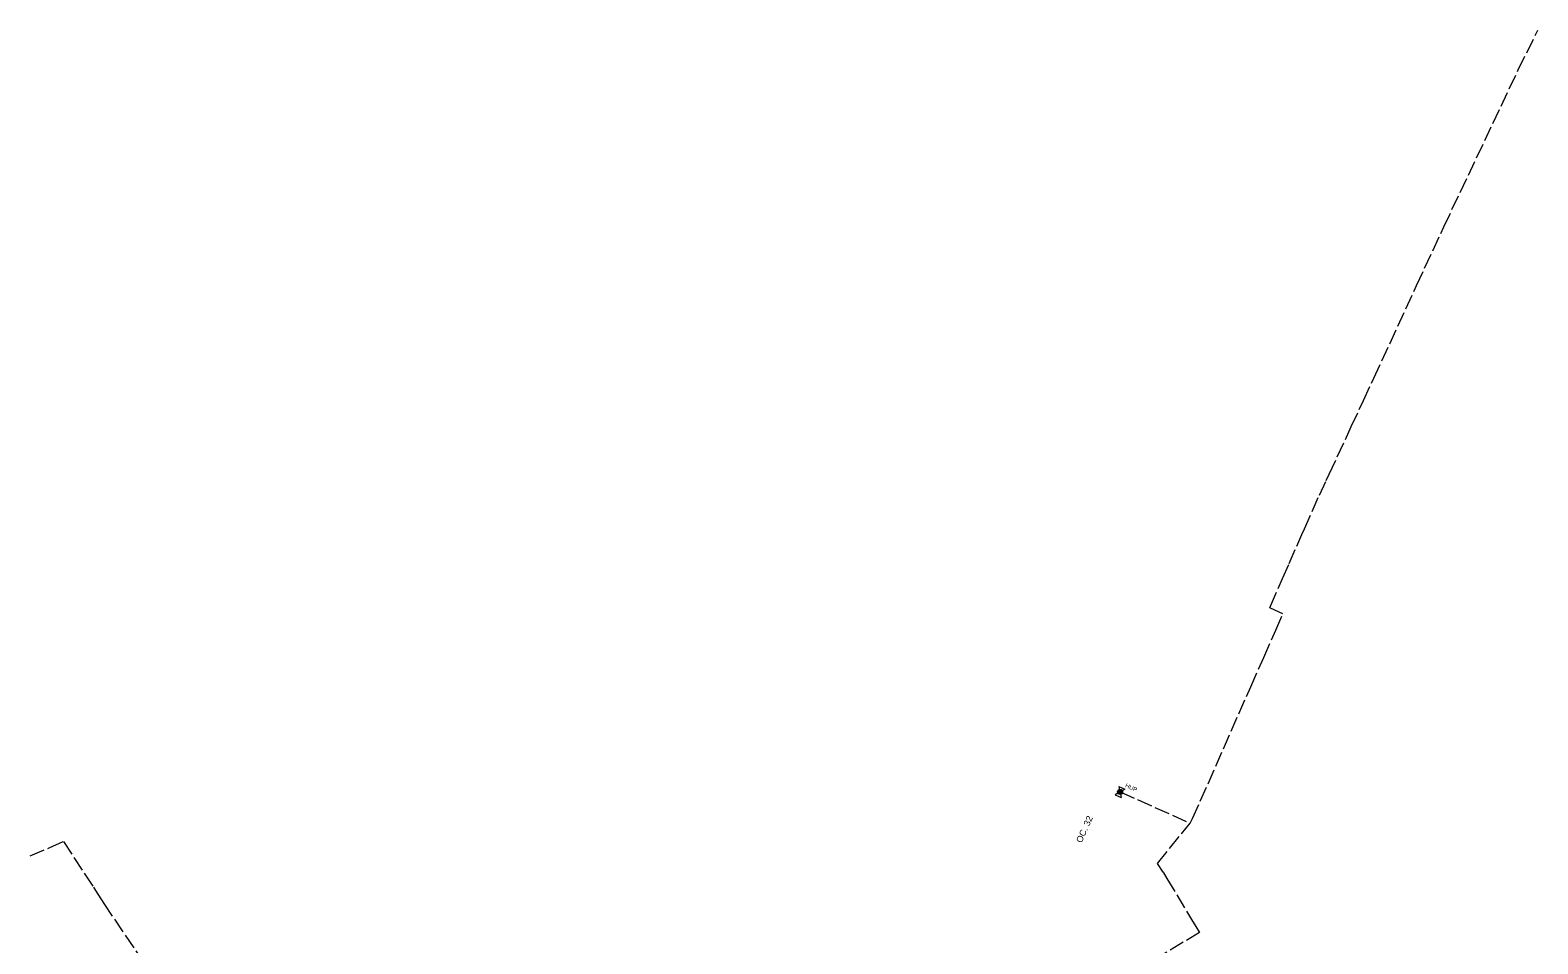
# Model space of a CAD drawing. Extents: x -688140 to -687678, y -1056859 to -1056384.
# Drawn here: x -688068.5 to -687890.7, y -1056491.8 to -1056384.1 of the extents above; entities that cross this region are included whole.
import ezdxf
from ezdxf.enums import TextEntityAlignment as Align

# ---------------------------------------------------------------- set-up
doc = ezdxf.new("R2010")
doc.units = 0
doc.header["$LTSCALE"] = 0.3
doc.linetypes.add('LONG_DASHED', pattern=[7.5, 6, -1.5])
for name, color, linetype, lineweight in [('12', 7, 'Continuous', 13), ('35', 7, 'LONG_DASHED', 13), ('50', 7, 'LONG_DASHED', 13)]:
    doc.layers.add(name, color=color, linetype=linetype, lineweight=lineweight)
doc.layers.add('15', color=7, linetype='Continuous')

msp = doc.modelspace()

# ---------------------------------------------------------------- linework, layer by layer
at = {"layer": '12'}
for p, q in [((-687939.43, -1056473.567), (-687940.576, -1056474.249)), ((-687940.133, -1056473.254), (-687939.873, -1056474.562)), ((-687940.133, -1056473.254), (-687939.43, -1056473.567)), ((-687940.576, -1056474.249), (-687939.873, -1056474.562))]:
    msp.add_line(p, q, dxfattribs=at)
for radius in [0.297, 0.223, 0.223, 0.112]:
    msp.add_circle((-687940.003, -1056473.908), radius, dxfattribs=at)
at = {"layer": '35'}
for points in [[(-687934.92, -1056483.379), (-687935.58, -1056482.33), (-687931.737, -1056477.588), (-687931.45, -1056477.058), (-687926.001, -1056464.708), (-687924.589, -1056461.507), (-687923.067, -1056458.056), (-687921.655, -1056454.855), (-687920.804, -1056452.925), (-687921.257, -1056452.721), (-687922.344, -1056452.206), (-687922.278, -1056452.013), (-687920.848, -1056448.766), (-687920.069, -1056446.995), (-687918.57, -1056443.591), (-687918.275, -1056442.92), (-687916.507, -1056438.952), (-687915.712, -1056437.226), (-687915.334, -1056436.453), (-687912.744, -1056430.863), (-687911.305, -1056427.776), (-687910.099, -1056425.159), (-687908.2, -1056421.083), (-687905.044, -1056414.213), (-687901.831, -1056407.322), (-687893.061, -1056388.815), (-687890.746, -1056384.135)], [(-688068.5, -1056481.45), (-688066.239, -1056480.491), (-688064.578, -1056479.739), (-688061.036, -1056485.154), (-688060.797, -1056485.528), (-688059.819, -1056487.056), (-688052.842, -1056497.398), (-688047.328, -1056505.525), (-688039.953, -1056516.851), (-688038.044, -1056518.922), (-688033.59, -1056520.156), (-688019.679, -1056523.9), (-688010.809, -1056526.484), (-688010.441, -1056526.59), (-688010.399, -1056526.602), (-688010.483, -1056528.798), (-688007.1, -1056529.75), (-688006.63, -1056529.98), (-688006.34, -1056530.44)], [(-687934.92, -1056483.379), (-687934.48, -1056484.1), (-687931.57, -1056488.93), (-687931.05, -1056489.78), (-687930.64, -1056490.47), (-687940.574, -1056496.498), (-687941.6, -1056497.12), (-687942.464, -1056497.696), (-687944.2, -1056498.69), (-687950.55, -1056502.49), (-687951.37, -1056502.98), (-687952.8, -1056503.81), (-687962, -1056509.53), (-687962.18, -1056509.64), (-687962.19, -1056509.625), (-687963.04, -1056508.39), (-687964.19, -1056506.75), (-687972.1, -1056511.04), (-687973.789, -1056512.111), (-687973.85, -1056512.15), (-687977.61, -1056514.19), (-687978.48, -1056514.66), (-687999.12, -1056527.17), (-688005.94, -1056531)]]:
    msp.add_lwpolyline(points, dxfattribs=at)
at = {"layer": '50'}
msp.add_line((-687940.003, -1056473.908), (-687931.737, -1056477.588), dxfattribs=at)

# ---------------------------------------------------------------- texts
at = {"layer": '12', "width": 0.9}
msp.add_text('HUP', height=0.5, rotation=335.999, dxfattribs=at).set_placement((-687938.785, -1056473.629), align=Align.CENTER)
at = {"layer": '15', "width": 1.05}
msp.add_text('OC. 32', height=0.75, rotation=66.002, dxfattribs=at).set_placement((-687944.537, -1056479.983))

doc.saveas('drawing.dxf')
